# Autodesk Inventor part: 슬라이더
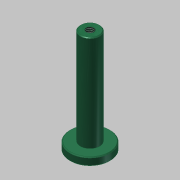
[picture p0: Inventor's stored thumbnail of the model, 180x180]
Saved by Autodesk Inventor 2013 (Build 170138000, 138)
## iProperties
Created: 2016-02
Part Number: 슬라이더
Material: 스테인리스강
Document SubType Name: Modeling
Designer: mduedu
Density: 8.08 g/cm^3
Mass: 72.5507 g
Surface Area: 37.669 cm^2
Volume: 8.97904 cm^3
Author: mduedu
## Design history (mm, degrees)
sketch "스케치1"
  geometry: C1 r 12.5 at (0, 0); 1 further point
  constraints: 1 centre point, 1 coincident
  dimensions: "d0" = 25 diameter of C1
extrude "돌출1" new body sketch "스케치1" distance "d1" = 5; taper "d2" = 0 deg
sketch "스케치2"
  geometry: C1 r 6 at (0, 0); 1 further point
  constraints: 1 centre point, 1 coincident
  dimensions: "d3" = 12 diameter of C1
extrude "돌출2" join sketch "스케치2" distance "d4" = 60; taper "d5" = 0 deg
chamfer "모따기1" distance "d6" = 0.5; stored, may be unused: second distance "d7" = 2, angle "d8" = 45 deg
hole "구멍1" diameter "d11" = 4.917; stored, may be unused: countersink angle "d15" = 90 deg, drill point angle "d17" = 118 deg; dims "d9" = 10, "d10" = 10, "d12" = 10, "d13" = 4, "d14" = 2, "d16" = 12
chamfer "모따기2" distance "d18" = 0.5; stored, may be unused: second distance "d19" = 2, angle "d20" = 45 deg
sketch "스케치3"
  geometry: L1 (-12.5, 4.5)-(-12, 5) reference; L2 (-12, 5)-(-6, 5) reference; L3 (-6, 5)-(-6, 64.5) reference; L4 (-6, 64.5)-(-5.5, 65) reference; L5 (-5.5, 65)-(-2.458, 65) reference; L6 (-2.458, 65)-(-2.458, 53) reference; L7 (-2.458, 53)-(0, 51.523) reference; L8 (0, 51.523)-(2.458, 53) reference; L9 (2.458, 53)-(2.458, 65) reference; L10 (2.458, 65)-(5.5, 65) reference; L11 (5.5, 65)-(6, 64.5) reference; L12 (6, 64.5)-(6, 5) reference; L13 (6, 5)-(12, 5) reference; L14 (12, 5)-(12.5, 4.5) reference; L15 (12.5, 4.5)-(12.5, 0.5) reference; L16 (12.5, 0.5)-(12, 0) reference; L17 (12, 0)-(-12, 0) reference; L18 (-12, 0)-(-12.5, 0.5) reference; L19 (-12.5, 0.5)-(-12.5, 4.5) reference; 1 further point
  node "절단 모서리 투영1"
node "솔리드1"
